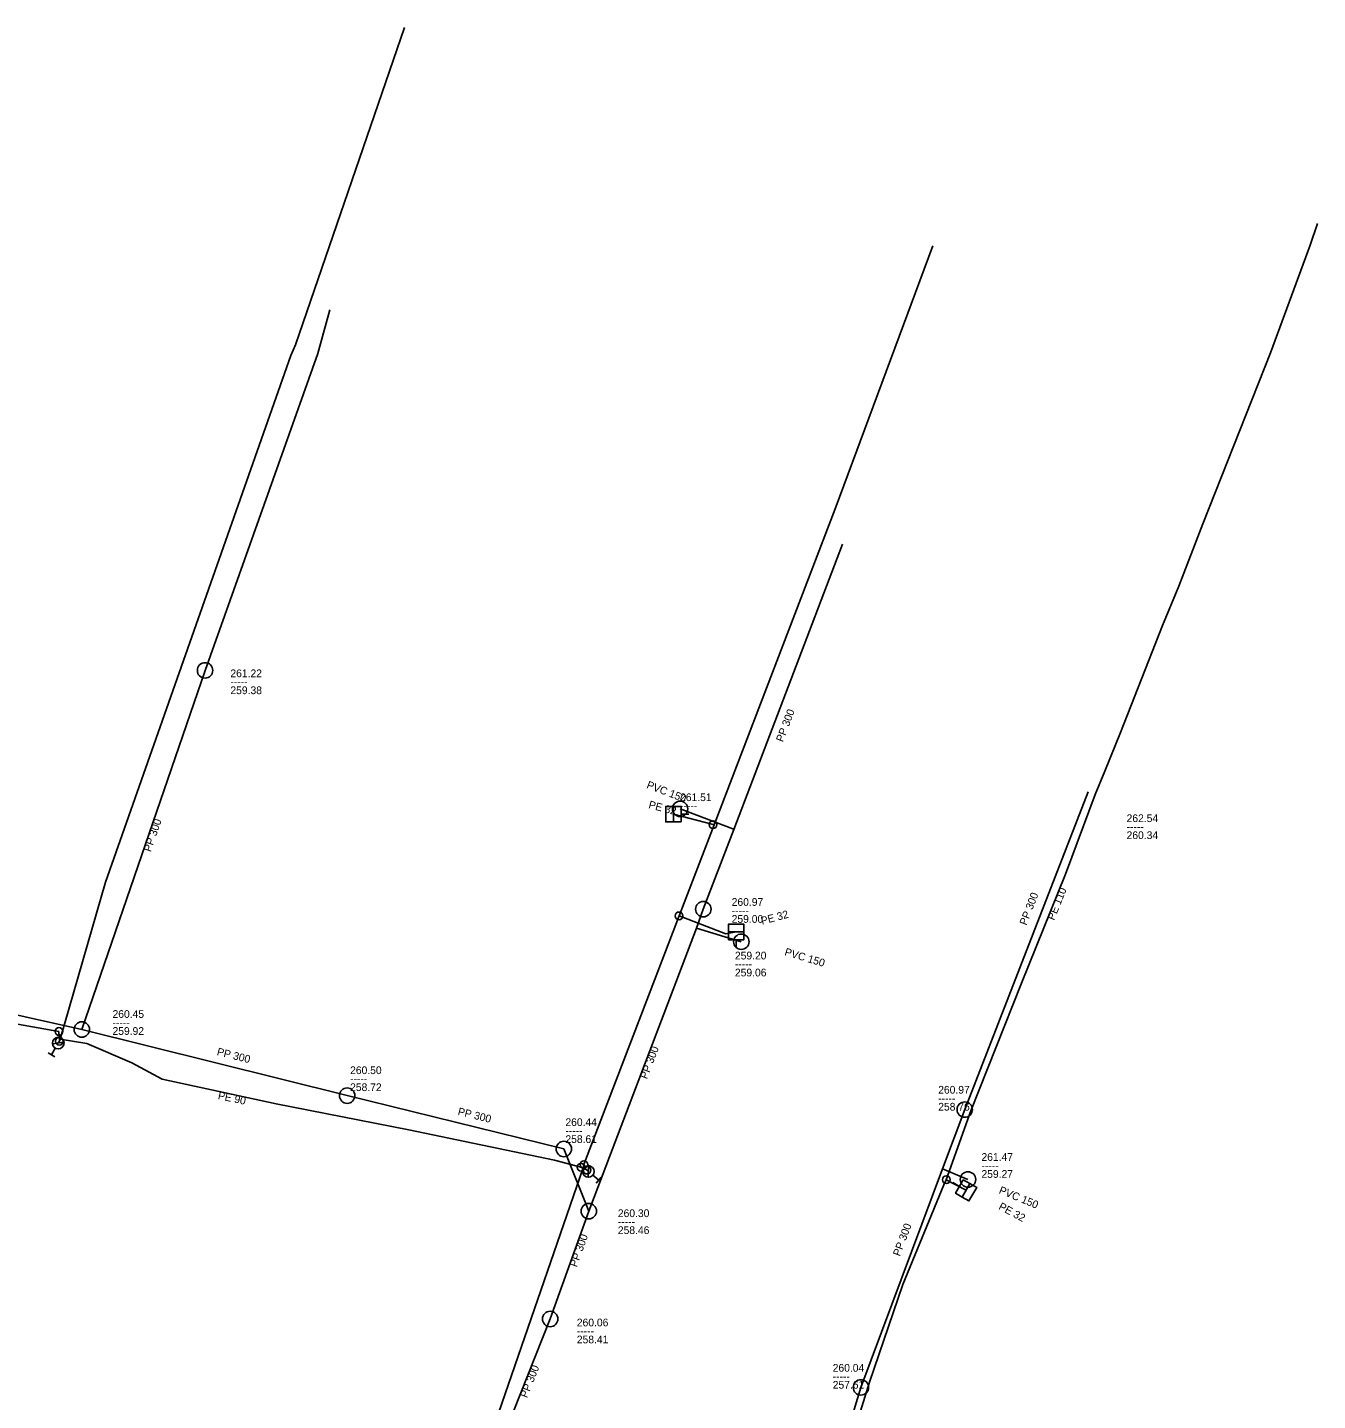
# Model space of a CAD drawing. Extents: x -771681 to -770485, y -1050143 to -1049574.
# Drawn here: x -770925.9 to -770758.6, y -1049898.6 to -1049720.5 of the extents above; entities that cross this region are included whole.
import ezdxf

# ---------------------------------------------------------------- set-up
doc = ezdxf.new("R2010")
doc.units = 0
doc.layers.add('Level 0', color=7, linetype='Continuous')

msp = doc.modelspace()

# ---------------------------------------------------------------- linework, layer by layer
at = {"layer": 'Level 0'}
for p, q in [((-770891.09, -1049761.68), (-770876.96, -1049720.52)), ((-770759.54, -1049748.77), (-770758.58, -1049745.92)), ((-770821.15, -1049782.94), (-770808.46, -1049748.85)), ((-770764.68, -1049762.7), (-770759.54, -1049748.77)), ((-770886.67, -1049757.14), (-770888.22, -1049762.8)), ((-770891.72, -1049763.05), (-770891.09, -1049761.68)), ((-770773.46, -1049784.87), (-770764.68, -1049762.7)), ((-770915.75, -1049831.34), (-770891.72, -1049763.05)), ((-770888.22, -1049762.8), (-770902.84, -1049803.89)), ((-770836.84, -1049823.92), (-770821.15, -1049782.94)), ((-770776.57, -1049792.98), (-770773.46, -1049784.87)), ((-770820.19, -1049787.53), (-770834.28, -1049824.5)), ((-770778.68, -1049798.06), (-770776.57, -1049792.98)), ((-770784.11, -1049811.95), (-770778.68, -1049798.06)), ((-770902.84, -1049803.89), (-770918.82, -1049850.46)), ((-770786.16, -1049816.95), (-770784.11, -1049811.95)), ((-770787.41, -1049820), (-770786.16, -1049816.95)), ((-770788.34, -1049819.62), (-770804.33, -1049860.84)), ((-770791.25, -1049830.32), (-770787.41, -1049820)), ((-770836.97, -1049823.89), (-770842.09, -1049822.53)), ((-770841.24, -1049821.84), (-770834.41, -1049824.45)), ((-770840.09, -1049822.53), (-770841.09, -1049822.53)), ((-770841.38, -1049835.72), (-770836.84, -1049823.92)), ((-770834.28, -1049824.5), (-770838.23, -1049834.85)), ((-770836.84, -1049823.92), (-770836.97, -1049823.89)), ((-770834.41, -1049824.45), (-770834.28, -1049824.5)), ((-770796.96, -1049844.45), (-770791.25, -1049830.32)), ((-770921.62, -1049851.72), (-770915.75, -1049831.34)), ((-770853.71, -1049867.97), (-770841.38, -1049835.72)), ((-770835.3, -1049838.04), (-770841.38, -1049835.72)), ((-770838.23, -1049834.85), (-770839.13, -1049837.33)), ((-770839.13, -1049837.33), (-770853.08, -1049874.01)), ((-770833.3, -1049839.08), (-770839.13, -1049837.33)), ((-770833.97, -1049837.81), (-770835.3, -1049838.04)), ((-770833.97, -1049839.81), (-770833.97, -1049838.81)), ((-770803.53, -1049861.01), (-770796.96, -1049844.45)), ((-770932.9, -1049847.34), (-770918.82, -1049850.46)), ((-770921.78, -1049850.71), (-770933.62, -1049848.6)), ((-770921.78, -1049850.71), (-770921.73, -1049851.97)), ((-770921.73, -1049851.97), (-770921.62, -1049851.72)), ((-770918.17, -1049852.29), (-770921.62, -1049851.72)), ((-770918.82, -1049850.46), (-770884.41, -1049859.03)), ((-770922.32, -1049853.99), (-770923.19, -1049853.49)), ((-770922.26, -1049852.87), (-770922.76, -1049853.74)), ((-770921.14, -1049852.11), (-770922.62, -1049852.33)), ((-770921.73, -1049851.97), (-770921.88, -1049852.22)), ((-770912.35, -1049854.76), (-770918.17, -1049852.29)), ((-770908.42, -1049856.88), (-770912.35, -1049854.76)), ((-770893.61, -1049860.08), (-770908.42, -1049856.88)), ((-770876.43, -1049863.47), (-770893.61, -1049860.08)), ((-770884.41, -1049859.03), (-770856.32, -1049865.95)), ((-770804.33, -1049860.84), (-770807.2, -1049868.53)), ((-770806.72, -1049869.93), (-770803.53, -1049861.01)), ((-770857.53, -1049867.42), (-770876.43, -1049863.47)), ((-770856.32, -1049865.95), (-770853.08, -1049874.01)), ((-770854.09, -1049868.32), (-770857.53, -1049867.42)), ((-770872.22, -1049921.74), (-770853.82, -1049868.4)), ((-770853.82, -1049868.4), (-770854.09, -1049868.32)), ((-770853.82, -1049868.4), (-770853.71, -1049867.97)), ((-770853.82, -1049868.4), (-770853.31, -1049868.69)), ((-770853.31, -1049868.69), (-770853.13, -1049868.86)), ((-770853.11, -1049868.11), (-770853.16, -1049869.61)), ((-770852.56, -1049869.34), (-770851.79, -1049869.98)), ((-770851.47, -1049869.6), (-770852.11, -1049870.37)), ((-770807.2, -1049868.53), (-770817.79, -1049896.87)), ((-770803.91, -1049869.9), (-770807.2, -1049868.53)), ((-770812.35, -1049883.52), (-770807.02, -1049870.58)), ((-770807.02, -1049870.58), (-770806.72, -1049869.93)), ((-770804.15, -1049871.31), (-770806.72, -1049869.93)), ((-770805.88, -1049870.31), (-770805.02, -1049870.81)), ((-770853.08, -1049874.01), (-770858.09, -1049887.99)), ((-770816.69, -1049896.18), (-770812.35, -1049883.52)), ((-770858.09, -1049887.99), (-770865.96, -1049907.86)), ((-770819.69, -1049905.97), (-770816.69, -1049896.18)), ((-770817.79, -1049896.87), (-770826.51, -1049925.68))]:
    msp.add_line(p, q, dxfattribs=at)
for points in [[(-770842.09, -1049823.53), (-770843.09, -1049823.53), (-770843.09, -1049821.53), (-770842.09, -1049821.53)], [(-770834.97, -1049837.81), (-770834.97, -1049836.81), (-770832.97, -1049836.81), (-770832.97, -1049837.81)], [(-770803.65, -1049870.44), (-770802.78, -1049870.94), (-770803.78, -1049872.68), (-770804.65, -1049872.18)]]:
    msp.add_lwpolyline(points, dxfattribs=at)
for points in [[(-770841.09, -1049823.53), (-770841.09, -1049821.53), (-770842.09, -1049821.53), (-770842.09, -1049823.53)], [(-770834.97, -1049838.81), (-770832.97, -1049838.81), (-770832.97, -1049837.81), (-770834.97, -1049837.81)], [(-770804.52, -1049869.94), (-770805.52, -1049871.68), (-770804.65, -1049872.18), (-770803.65, -1049870.44)]]:
    msp.add_lwpolyline(points, close=True, dxfattribs=at)
for centre, radius in [((-770902.84, -1049803.89), 1), ((-770841.24, -1049821.84), 1), ((-770836.97, -1049823.89), 0.5), ((-770838.23, -1049834.85), 1), ((-770841.38, -1049835.72), 0.5), ((-770833.3, -1049839.08), 1), ((-770918.82, -1049850.46), 1), ((-770921.88, -1049852.22), 0.75), ((-770921.78, -1049850.71), 0.5), ((-770921.73, -1049851.97), 0.5), ((-770884.41, -1049859.03), 1), ((-770804.33, -1049860.84), 1), ((-770856.32, -1049865.95), 1), ((-770854.09, -1049868.32), 0.5), ((-770853.71, -1049867.97), 0.5), ((-770853.13, -1049868.86), 0.75), ((-770853.31, -1049868.69), 0.5), ((-770806.72, -1049869.93), 0.5), ((-770803.91, -1049869.9), 1), ((-770853.08, -1049874.01), 1), ((-770858.09, -1049887.99), 1), ((-770817.79, -1049896.87), 1)]:
    msp.add_circle(centre, radius, dxfattribs=at)

# ---------------------------------------------------------------- texts
for s, p in [('-----', (-770899.55, -1049805.87)), ('261.22', (-770899.55, -1049804.77)), ('259.38', (-770899.55, -1049806.97)), ('-----', (-770841.24, -1049821.94)), ('261.51', (-770841.24, -1049820.84)), ('262.54', (-770783.34, -1049823.56)), ('-----', (-770783.34, -1049824.66)), ('260.34', (-770783.34, -1049825.76)), ('260.97', (-770834.55, -1049834.42)), ('-----', (-770834.55, -1049835.52)), ('259.00', (-770834.55, -1049836.62)), ('259.20', (-770834.13, -1049841.37)), ('-----', (-770834.13, -1049842.47)), ('259.06', (-770834.13, -1049843.57)), ('260.45', (-770914.84, -1049848.95)), ('-----', (-770914.84, -1049850.05)), ('259.92', (-770914.84, -1049851.15)), ('260.50', (-770884.03, -1049856.24)), ('-----', (-770884.03, -1049857.34)), ('258.72', (-770884.03, -1049858.44)), ('260.97', (-770807.77, -1049858.77)), ('-----', (-770807.77, -1049859.87)), ('258.76', (-770807.77, -1049860.97)), ('260.44', (-770856.11, -1049862.97)), ('-----', (-770856.11, -1049864.07)), ('258.61', (-770856.11, -1049865.17)), ('261.47', (-770802.16, -1049867.49)), ('-----', (-770802.16, -1049868.59)), ('259.27', (-770802.16, -1049869.69)), ('260.30', (-770849.31, -1049874.78)), ('-----', (-770849.31, -1049875.88)), ('258.46', (-770849.31, -1049876.98)), ('260.06', (-770854.63, -1049888.95)), ('-----', (-770854.63, -1049890.05)), ('258.41', (-770854.63, -1049891.15)), ('260.04', (-770821.45, -1049894.83)), ('-----', (-770821.45, -1049895.93)), ('257.61', (-770821.45, -1049897.03))]:
    msp.add_text(s, height=1, dxfattribs=at).set_placement(p)
for s, rotation, p in [('PP 300', 69.111, (-770827.91, -1049813.25)), ('PVC 150', 338.962, (-770845.67, -1049819.12)), ('PE 32', 345.124, (-770845.4, -1049821.73)), ('PP 300', 71.061, (-770909.88, -1049827.5)), ('PE 110', 67.996, (-770792.74, -1049836.37)), ('PP 300', 68.798, (-770796.34, -1049837.02)), ('PE 32', 15, (-770830.61, -1049836.88)), ('PVC 150', 343.292, (-770827.77, -1049840.81)), ('PP 300', 346.015, (-770901.37, -1049853.77)), ('PP 300', 69.177, (-770845.53, -1049856.96)), ('PE 90', 347.808, (-770901.23, -1049859.46)), ('PP 300', 346.161, (-770870.13, -1049861.52)), ('PVC 150', 337.393, (-770799.98, -1049871.66)), ('PE 32', 331.766, (-770800.03, -1049873.71)), ('PP 300', 69.51, (-770812.74, -1049879.93)), ('PP 300', 70.284, (-770854.64, -1049881.34)), ('PP 300', 68.348, (-770861.09, -1049898.3))]:
    msp.add_text(s, height=1, rotation=rotation, dxfattribs=at).set_placement(p)

doc.saveas('drawing.dxf')
